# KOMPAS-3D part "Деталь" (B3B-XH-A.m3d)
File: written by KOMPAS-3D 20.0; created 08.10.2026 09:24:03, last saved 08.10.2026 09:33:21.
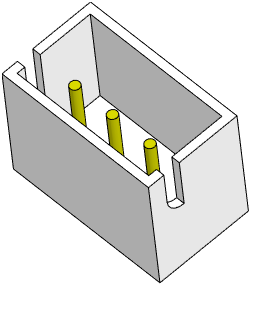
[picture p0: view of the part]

Document properties: Полное имя файла: D:\RicWork\Project-EPS32\box_compas\B3B-XH-A.m3d

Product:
- Part/product: Деталь
    Масса: 0.00117184

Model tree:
1. Эскиз:1
2. Элемент выдавливания:1
     Расстояние 1 = 7
3. Эскиз:2  (with: Элемент выдавливания:1)
4. Элемент выдавливания:2
     Расстояние 2 = 6
5. Эскиз:3  (with: Элемент выдавливания:1)
6. Элемент выдавливания:3
     Расстояние 2 = 9.9
7. Скругление:1  (with: Элемент выдавливания:3)
     Радиус = 1
8. Эскиз:4  (with: Элемент выдавливания:1)
9. Элемент выдавливания:4
     Расстояние 1 = 3.4
10. Массив по сетке:1  (with: Элемент выдавливания:4, Эскиз:4)  (3 pattern instances)
     Шаг 1 = 10; Угол раствора = -90; Шаг 2 = 2.54
11. Эскиз:5  (with: Элемент выдавливания:2, Элемент выдавливания:4)
12. Элемент выдавливания:5
     Расстояние 1 = 5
